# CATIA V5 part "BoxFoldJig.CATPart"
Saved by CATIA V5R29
Part number: BoxFoldJig
Bounding box of the stored display mesh (mm): x -128.607 to 128.607, y -217.251 to 131.984, z 141.34 to 260
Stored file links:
  C:\Users\Administrator\Desktop\프로젝트\Boxfold\BoxFoldJig.CATPart
  C:\Users\Administrator\Desktop\프로젝트\Boxfold\JigBraket.CATPart
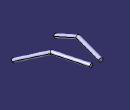
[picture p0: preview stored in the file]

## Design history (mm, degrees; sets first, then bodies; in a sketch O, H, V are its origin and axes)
Body1 (main body)
  DatumCurve1 to DatumCurve6
  Plane1: type Angle, RefPlane yz-plane, Direction Z axis, Angle 15
  Plane2: type Offset, RefPlane Plane1, Offset 60
  DatumCurve7
  Sketch1 on Plane2, origin (58.4084, 13.839, 0), H (-0.2588, 0.9659, 0), V (0, 0, 1)
    point P1 (119.6332, 250)
    line L1 (119.6332, 250) -> (-60.3668, 250)
    line L2 (-60.3668, 250) -> (-233.5719, 150)
    point P3 (-233.5719, 150)
    reference projected line E1 (-387.8686, 200) -> (-98.0909, 200) from edge of DatumCurve7
    angle L2 L1 = 150
    length L2 = 200
    length L1 = 180
    distance L1 E1 = 50
    distance P3 V = 233.5719
    horizontal: L1 H
  Plane3: type Angle, RefPlane Plane2, Direction Z axis, Angle 90
  Plane4: type OffsetPt, RefPlane Plane3, RefPoint Sketch1.P1
  Sketch2 on Plane4, origin (-36.6395, 112.2244, 0), H (-0.9659, -0.2588, 0), V (0, 0, 1)
    circle A1 centre (-66.3453, 250) radius 10
    point P1 (-66.3453, 250)
    reference projected point E1 (-66.3453, 250) from Sketch1.P1
    radius A1 = 10
    coincidence: P1 E1
  Rib1: profile Sketch2, centre curve Sketch1
  Mirror1: of Rib1, about yz-plane
  Plane5: type Offset, RefPlane Plane4, Offset 30, reversed
  DatumCurve8
  Plane6: type Offset, RefPlane Plane5, Offset 20
  DatumCurve9 to DatumCurve11
  DatumSurface1
  DatumCurve12
  DatumCurve13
